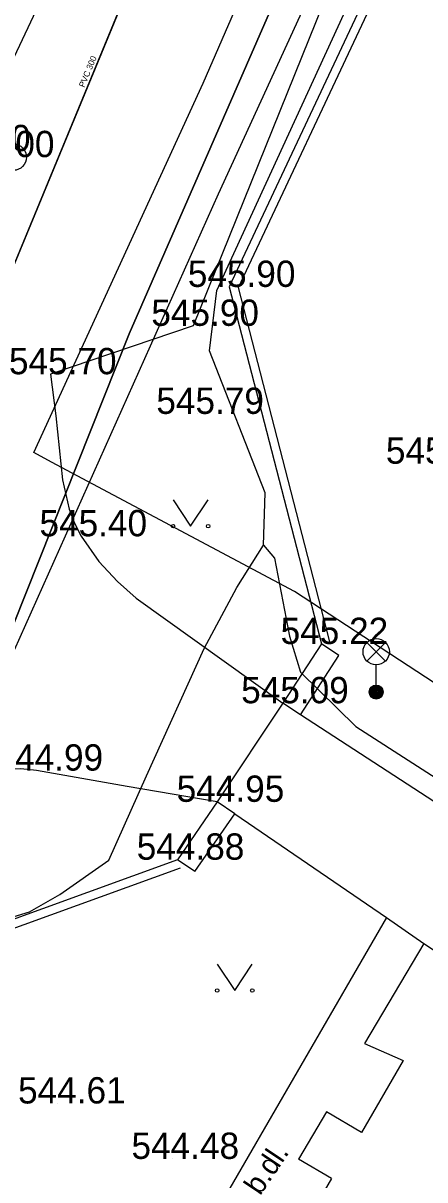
# Model space of a CAD drawing. Extents: x -669393 to -668650, y -1126925 to -1126294.
# Drawn here: x -668939.81 to -668928.36, y -1126583.06 to -1126550.08 of the extents above; entities that cross this region are included whole.
import ezdxf

# ---------------------------------------------------------------- set-up
doc = ezdxf.new("R2010")
doc.units = 0
for name, color, linetype in [('G_Bod_tecka', 7, 'Continuous'), ('G_Bod_vyska', 7, 'Continuous'), ('G_Objekty_technicke', 7, 'Continuous'), ('G_Plochy_zpevnene', 7, 'Continuous'), ('G_Ploty', 7, 'Continuous'), ('G_Ploty_vstupy', 7, 'Continuous'), ('G_Popisy_povrchu', 7, 'Continuous'), ('G_Site-vodovod', 7, 'Continuous'), ('G_Z_KANAL_podz_kotovane', 7, 'Continuous'), ('G_Z_PLYNY_podz_geodeticky', 7, 'Continuous'), ('G_Z_SPOJE_podz_geodeticky', 7, 'Continuous'), ('G_Z_SPOJE_podz_kotovane', 7, 'Continuous'), ('G_Z_SPOJE_podz_priblizne', 7, 'Continuous'), ('G_Z_SPOJE_podz_zahozene', 7, 'Continuous'), ('G_Z_VODA_podz_kotovane', 7, 'Continuous'), ('G_Zelen-Znacky', 7, 'Continuous'), ('Vrstva 11', 7, 'Continuous'), ('Vrstva 12', 7, 'Continuous'), ('Vrstva 26', 7, 'Continuous'), ('Vrstva 3', 7, 'Continuous')]:
    doc.layers.add(name, color=color, linetype=linetype)

msp = doc.modelspace()

# ---------------------------------------------------------------- linework, layer by layer
at = {"layer": 'G_Bod_tecka'}
for p, q in [((-668933.94, -1126557.6), (-668933.94, -1126557.6)), ((-668934.97, -1126558.71), (-668934.97, -1126558.71)), ((-668939.03, -1126560.09), (-668939.03, -1126560.09)), ((-668934.85, -1126561.22), (-668934.85, -1126561.22)), ((-668938.16, -1126564.71), (-668938.16, -1126564.71)), ((-668931.31, -1126567.78), (-668931.31, -1126567.78)), ((-668932.41, -1126569.47), (-668932.41, -1126569.47)), ((-668939.43, -1126571.39), (-668939.43, -1126571.39)), ((-668934.28, -1126572.28), (-668934.28, -1126572.28)), ((-668935.41, -1126573.93), (-668935.41, -1126573.93)), ((-668938.84, -1126580.88), (-668938.84, -1126580.88)), ((-668935.56, -1126582.46), (-668935.56, -1126582.46))]:
    msp.add_line(p, q, dxfattribs=at)
at = {"layer": 'G_Objekty_technicke'}
for points in [[(-668930.015, -1126567.735), (-668929.485, -1126568.265)], [(-668930.015, -1126568.265), (-668929.485, -1126567.735)], [(-668929.75, -1126569.15), (-668929.75, -1126568.375)]]:
    msp.add_lwpolyline(points, dxfattribs=at)
for centre, radius in [((-668929.75, -1126568), 0.375), ((-668929.75, -1126569.15), 0.2), ((-668929.75, -1126569.15), 0.18), ((-668929.75, -1126569.15), 0.16), ((-668929.75, -1126569.15), 0.14), ((-668929.75, -1126569.15), 0.12), ((-668929.75, -1126569.15), 0.1), ((-668929.75, -1126569.15), 0.08), ((-668929.75, -1126569.15), 0.06), ((-668929.75, -1126569.15), 0.04), ((-668929.75, -1126569.15), 0.02)]:
    msp.add_circle(centre, radius, dxfattribs=at)
at = {"layer": 'G_Plochy_zpevnene'}
msp.add_line((-668929.46, -1126575.58), (-668928.39, -1126576.32), dxfattribs=at)
for points in [[(-668924.25, -1126532.15), (-668934.97, -1126558.71)], [(-668934.97, -1126558.71), (-668939.03, -1126560.09)], [(-668939.03, -1126560.09), (-668938.88, -1126561.28), (-668938.69, -1126563.1), (-668938.5, -1126563.94), (-668938.35, -1126564.34), (-668938.16, -1126564.71), (-668937.65, -1126565.43), (-668937.12, -1126566), (-668936.59, -1126566.47), (-668932.41, -1126569.47)], [(-668927.73, -1126572.52), (-668931.91, -1126569.8)], [(-668934.28, -1126572.28), (-668936.85, -1126571.84), (-668939.43, -1126571.39), (-668939.88, -1126571.34), (-668940.3, -1126571.35), (-668940.71, -1126571.41), (-668941.46, -1126571.62), (-668942.11, -1126571.92), (-668942.65, -1126572.24), (-668943.1, -1126572.57), (-668943.83, -1126573.24), (-668944.31, -1126573.8), (-668944.62, -1126574.24), (-668945, -1126574.93), (-668945.26, -1126575.64), (-668948.71, -1126588.29), (-668952.16, -1126600.95)], [(-668933.78, -1126572.62), (-668929.46, -1126575.58)], [(-668929.46, -1126575.58), (-668936.78, -1126588.24)], [(-668928.39, -1126576.32), (-668930.08, -1126579.17)], [(-668928.39, -1126576.32), (-668916.99, -1126583.81), (-668914.09, -1126585.73)], [(-668930.08, -1126579.17), (-668928.98, -1126579.65)], [(-668928.98, -1126579.65), (-668930.17, -1126581.71)], [(-668931.17, -1126581.12), (-668931.96, -1126582.47)], [(-668930.17, -1126581.71), (-668931.17, -1126581.12)], [(-668931.02, -1126583.02), (-668931.96, -1126582.47)], [(-668931.02, -1126583.02), (-668932.18, -1126585.02)]]:
    msp.add_lwpolyline(points, dxfattribs=at)
at = {"layer": 'G_Ploty'}
for p, q in [((-668933.67, -1126557.62), (-668921.06, -1126530.75)), ((-668922.27, -1126532.74), (-668933.94, -1126557.6)), ((-668933.94, -1126557.6), (-668931.31, -1126567.78)), ((-668931.07, -1126567.72), (-668933.67, -1126557.62)), ((-668931.31, -1126567.78), (-668932.41, -1126569.47)), ((-668930.81, -1126568.11), (-668931.31, -1126567.78)), ((-668931.91, -1126569.8), (-668930.81, -1126568.11)), ((-668931.91, -1126569.8), (-668932.41, -1126569.47)), ((-668934.28, -1126572.28), (-668935.41, -1126573.93)), ((-668933.78, -1126572.62), (-668934.28, -1126572.28)), ((-668934.92, -1126574.27), (-668933.78, -1126572.62)), ((-668935.41, -1126573.93), (-668943.35, -1126576.81)), ((-668934.92, -1126574.27), (-668935.41, -1126573.93)), ((-668943.15, -1126577), (-668935.33, -1126574.16))]:
    msp.add_line(p, q, dxfattribs=at)
at = {"layer": 'G_Ploty_vstupy'}
msp.add_line((-668932.41, -1126569.47), (-668934.28, -1126572.28), dxfattribs=at)
at = {"layer": 'G_Site-vodovod'}
msp.add_circle((-668940.09, -1126553.9), 0.375, dxfattribs=at)
at = {"layer": 'G_Z_KANAL_podz_kotovane'}
msp.add_line((-668932.38, -1126538.33), (-668942.68, -1126563.27), dxfattribs=at)
at = {"layer": 'G_Z_PLYNY_podz_geodeticky'}
msp.add_lwpolyline([(-668912.46, -1126577.78), (-668926.37, -1126570.02), (-668932.08, -1126566.28), (-668939, -1126562.6), (-668939.51, -1126562.32), (-668934.68, -1126551.79), (-668930.03, -1126541.08), (-668926.36, -1126532.59), (-668924.43, -1126528.03)], dxfattribs=at)
at = {"layer": 'G_Z_SPOJE_podz_geodeticky'}
msp.add_lwpolyline([(-668965.71, -1126659.23), (-668961.42, -1126636.58), (-668943.94, -1126576.61), (-668934.24, -1126554.95), (-668916.63, -1126516.53), (-668915.06, -1126512.35), (-668913.11, -1126502.62)], dxfattribs=at)
at = {"layer": 'G_Z_SPOJE_podz_kotovane'}
for points in [[(-668932.96, -1126564.96), (-668932.91, -1126563.47), (-668934.5, -1126559.42), (-668934.29, -1126557.7), (-668928.08, -1126544.17), (-668918.61, -1126523.92), (-668919.46, -1126523.43), (-668929.74, -1126519.37), (-668931.69, -1126518.41), (-668930.74, -1126513.2), (-668929.53, -1126509.88), (-668929.28, -1126508.54), (-668930.09, -1126507.23), (-668935.77, -1126503.73), (-668940.29, -1126501.53), (-668949.23, -1126497.98), (-668963.68, -1126493.08), (-668964.51, -1126492.65), (-668965.05, -1126492.07), (-668969, -1126491.19), (-668982.26, -1126489.32)], [(-668967.21, -1126674.78), (-668966.11, -1126667.11), (-668964.1, -1126654.97), (-668963.7, -1126653.53), (-668962.9, -1126653.19), (-668960.93, -1126641.59), (-668958.61, -1126631.73), (-668954.53, -1126631.88), (-668949.06, -1126611.36), (-668952.94, -1126608.03), (-668951.09, -1126603.92), (-668950.82, -1126601.67), (-668943.9, -1126577.58), (-668943.62, -1126576.63), (-668939.63, -1126575.42), (-668938.77, -1126574.92), (-668937.37, -1126573.94), (-668936.3, -1126571.54), (-668934.65, -1126567.91), (-668933.72, -1126566.17), (-668932.96, -1126564.96)], [(-668932.96, -1126564.96), (-668932.65, -1126565.33), (-668932.22, -1126567.56), (-668931.91, -1126568.58), (-668930.33, -1126570.13), (-668917.9, -1126578.13), (-668902.31, -1126587.99), (-668902.19, -1126588.94), (-668904.52, -1126592.26), (-668896.35, -1126597.92), (-668895.78, -1126599.5), (-668896.47, -1126601.19), (-668899.62, -1126606.3)]]:
    msp.add_lwpolyline(points, dxfattribs=at)
at = {"layer": 'G_Z_SPOJE_podz_priblizne'}
msp.add_lwpolyline([(-668965.71, -1126659.23), (-668961.42, -1126636.58), (-668943.94, -1126576.61), (-668934.24, -1126554.95), (-668916.63, -1126516.53), (-668915.06, -1126512.35), (-668913.11, -1126502.62)], dxfattribs=at)
at = {"layer": 'G_Z_SPOJE_podz_zahozene'}
for p, q in [((-668936.79, -1126558.94), (-668925.15, -1126532.27)), ((-668947.06, -1126584.73), (-668936.79, -1126558.94))]:
    msp.add_line(p, q, dxfattribs=at)
at = {"layer": 'G_Z_VODA_podz_kotovane'}
msp.add_lwpolyline([(-668911.63, -1126458.38), (-668911.94, -1126472.87), (-668917.84, -1126504.71), (-668919.43, -1126508.14), (-668925.09, -1126520.35), (-668931.13, -1126532.07), (-668941.27, -1126553.58), (-668941.86, -1126555.28), (-668944.85, -1126563.31), (-668947.04, -1126570.29), (-668952.04, -1126588.69), (-668955.63, -1126601.9), (-668956.77, -1126606.11), (-668961.43, -1126623.79), (-668964.55, -1126637.99), (-668966, -1126644.81), (-668969.29, -1126661.42), (-668971.68, -1126675.88)], dxfattribs=at)
at = {"layer": 'G_Zelen-Znacky'}
for points in [[(-668935.54, -1126563.67), (-668935.04, -1126564.42)], [(-668935.04, -1126564.42), (-668934.54, -1126563.67)], [(-668934.28, -1126576.91), (-668933.78, -1126577.66)], [(-668933.78, -1126577.66), (-668933.28, -1126576.91)]]:
    msp.add_lwpolyline(points, dxfattribs=at)
for centre in [(-668935.54, -1126564.42), (-668934.54, -1126564.42), (-668934.28, -1126577.66), (-668933.28, -1126577.66)]:
    msp.add_circle(centre, 0.05, dxfattribs=at)
at = {"layer": 'Vrstva 11'}
for points in [[(-668928.464, -1126509.545), (-668930.126, -1126515.891), (-668931.768, -1126520.514), (-668921.6, -1126524.127), (-668925.153, -1126532.268), (-668936.793, -1126558.936), (-668947.061, -1126584.729), (-668948.658, -1126590.658), (-668951.548, -1126601.392), (-668954.915, -1126614.718), (-668959.645, -1126633.436), (-668961.508, -1126641.36), (-668963.676, -1126652.148), (-668963.8, -1126654.117), (-668964.163, -1126659.861), (-668964.494, -1126665.114), (-668965.444, -1126668.273), (-668966.205, -1126676.085)], [(-668951.548, -1126601.392), (-668948.658, -1126590.658), (-668947.061, -1126584.729), (-668936.793, -1126558.936), (-668925.153, -1126532.268), (-668921.6, -1126524.127), (-668919.327, -1126524.437), (-668915.311, -1126525.848), (-668896.577, -1126530.077)]]:
    msp.add_lwpolyline(points, dxfattribs=at)
at = {"layer": 'Vrstva 12'}
msp.add_line((-668932.375, -1126538.327), (-668942.676, -1126563.268), dxfattribs=at)
at = {"layer": 'Vrstva 26'}
msp.add_lwpolyline([(-668911.629, -1126458.384), (-668911.94, -1126472.871), (-668917.84, -1126504.71), (-668919.428, -1126508.136), (-668925.09, -1126520.35), (-668931.13, -1126532.07), (-668941.27, -1126553.58), (-668941.858, -1126555.282), (-668944.85, -1126563.31), (-668947.04, -1126570.29), (-668952.039, -1126588.693), (-668955.626, -1126601.898), (-668956.767, -1126606.112), (-668961.43, -1126623.79), (-668964.551, -1126637.993), (-668965.997, -1126644.809), (-668969.289, -1126661.422), (-668971.679, -1126675.884)], dxfattribs=at)

# ---------------------------------------------------------------- texts
at = {"layer": 'G_Bod_vyska'}
for s, p in [('0.00', (-668941.55, -1126553.73)), ('0.00', (-668940.87, -1126553.9)), ('545.90', (-668935.118, -1126557.6)), ('545.90', (-668936.158, -1126558.71)), ('545.70', (-668940.216, -1126560.09)), ('545.79', (-668936.016, -1126561.22)), ('545.42', (-668929.474, -1126562.64)), ('545.40', (-668939.346, -1126564.71)), ('545.22', (-668932.474, -1126567.78)), ('545.09', (-668933.598, -1126569.47)), ('544.99', (-668940.598, -1126571.39)), ('544.95', (-668935.436, -1126572.28)), ('544.88', (-668936.574, -1126573.93)), ('544.61', (-668939.956, -1126580.88)), ('544.48', (-668936.724, -1126582.46))]:
    msp.add_text(s, height=0.75, dxfattribs=at).set_placement(p)
at = {"layer": 'G_Popisy_povrchu'}
msp.add_text('b.dl.', height=0.6, rotation=56.1089, dxfattribs=at).set_placement((-668933.057, -1126583.527))
at = {"layer": 'Vrstva 3'}
msp.add_text('PVC 300', height=0.1755, rotation=67.5607, dxfattribs=at).set_placement((-668938.068, -1126551.928))

doc.saveas('drawing.dxf')
